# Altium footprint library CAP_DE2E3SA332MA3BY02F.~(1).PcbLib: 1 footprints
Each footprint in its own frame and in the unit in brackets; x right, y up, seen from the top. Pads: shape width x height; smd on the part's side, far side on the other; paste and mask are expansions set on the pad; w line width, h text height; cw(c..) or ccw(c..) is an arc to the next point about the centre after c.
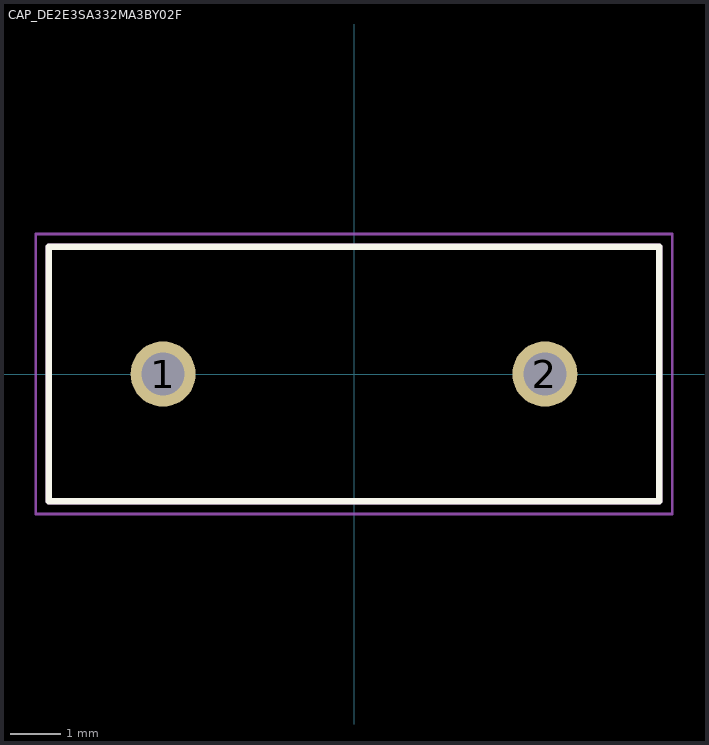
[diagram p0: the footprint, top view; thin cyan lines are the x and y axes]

## CAP_DE2E3SA332MA3BY02F [mm]
pads (2):
  round 1.28 hole 0.85: 1(-3.75,0) 2(3.75,0)
Top Overlay:
  lines w0.127: -6,-2.5 -6,2.5 6,2.5 6,-2.5 -6,-2.5
Mechanical 13:
  lines w0.127: -6,-2.5 -6,2.5 6,2.5 6,-2.5 -6,-2.5
Mechanical 15:
  lines w0.05: -6.25,-2.75 -6.25,2.75 6.25,2.75 6.25,-2.75 -6.25,-2.75
3D body "step_temp.STEP": height 15, standoff -25, extent -6,-2.5 6,2.5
